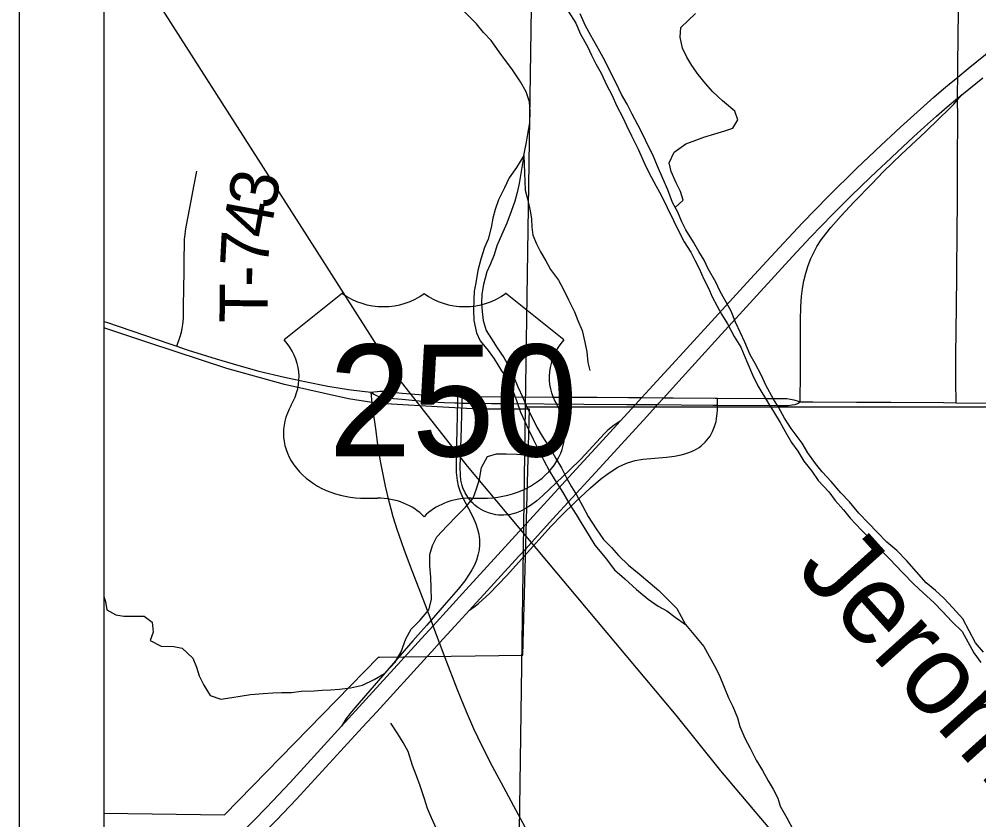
# Model space of a CAD drawing. Extents: x 0 to 34, y 0 to 22.
# Drawn here: x 9.008 to 10.139, y 9.788 to 10.732 of the extents above; entities that cross this region are included whole.
import ezdxf

# ---------------------------------------------------------------- set-up
doc = ezdxf.new("R2010")
doc.units = 0
for name, color, linetype in [('GM_X_Corporation', 7, 'Continuous'), ('GM_X_County_Road', 7, 'Continuous'), ('GM_X_Interchange_Ramps', 7, 'Continuous'), ('GM_X_Interstate_Route', 7, 'Continuous'), ('GM_X_Major_River', 7, 'Continuous'), ('GM_X_Major_River_Text', 7, 'Continuous'), ('GM_X_Minor_River', 7, 'Continuous'), ('GM_X_Rail_Line', 7, 'Continuous'), ('GM_X_Section', 7, 'Continuous'), ('GM_X_Township_Road', 7, 'Continuous'), ('GM_X_Township_Road_Text', 7, 'Continuous'), ('GM_X_US_Location', 7, 'Continuous'), ('GM_X_US_Route', 7, 'Continuous'), ('GM_X_US_Shield', 7, 'Continuous'), ('SH_Data', 7, 'Continuous')]:
    doc.layers.add(name, color=color, linetype=linetype)

msp = doc.modelspace()

# ---------------------------------------------------------------- linework, layer by layer
at = {"layer": 'GM_X_Corporation'}
msp.add_lwpolyline([(9.1079, 10.3684), (9.1079, 9.7958), (9.2501, 9.7938), (9.4314, 9.9801), (9.4329, 9.9801), (9.6019, 9.9824), (9.6097, 10.2726), (9.5496, 10.2726), (9.5073, 10.2746), (9.4404, 10.2788), (9.4239, 10.2802), (9.3964, 10.2847), (9.3206, 10.3014), (9.2529, 10.3204), (9.1608, 10.3507)], close=True, dxfattribs=at)
at = {"layer": 'GM_X_County_Road'}
msp.add_line((9.4241, 10.2795), (9.4228, 10.2923), dxfattribs=at)
for points in [[(9.5103, 9.9792), (9.5036, 9.9968), (9.4982, 10.0112), (9.496, 10.017), (9.4935, 10.0236), (9.4861, 10.0432), (9.4695, 10.0867), (9.4617, 10.1071), (9.4536, 10.1306), (9.449, 10.1455), (9.444, 10.1635), (9.4398, 10.1817), (9.4343, 10.2092), (9.4317, 10.2245), (9.4283, 10.2492), (9.4251, 10.2707), (9.4241, 10.2795)], [(9.6071, 9.7743), (9.5939, 9.7989), (9.5792, 9.8263), (9.5659, 9.8509), (9.5533, 9.8758), (9.544, 9.8955), (9.5353, 9.9155), (9.5249, 9.9415), (9.5103, 9.9792)]]:
    msp.add_lwpolyline(points, dxfattribs=at)
at = {"layer": 'GM_X_Interchange_Ramps'}
for points in [[(9.9288, 10.281), (9.9289, 10.295), (9.9291, 10.302), (9.9293, 10.3126), (9.9292, 10.3776), (9.9295, 10.3931), (9.9303, 10.4054), (9.9315, 10.4147), (9.9332, 10.4238), (9.9354, 10.4328), (9.9382, 10.4417), (9.9415, 10.4503), (9.9455, 10.4587), (9.9485, 10.4641), (9.9535, 10.472), (9.959, 10.4794), (9.9648, 10.4867), (9.9771, 10.5006), (9.9919, 10.5165), (10.0135, 10.5387), (10.0268, 10.5522), (10.0482, 10.5732), (10.0764, 10.5997), (10.0929, 10.6156), (10.1038, 10.626), (10.1099, 10.6322), (10.1145, 10.6373), (10.1195, 10.6432)], [(9.5247, 10.2879), (9.5247, 10.2869), (9.5246, 10.2799), (9.5243, 10.2693), (9.5242, 10.2631), (9.5239, 10.2506), (9.5237, 10.2288), (9.523, 10.2069), (9.5232, 10.1976), (9.5242, 10.1883), (9.5255, 10.1822), (9.5273, 10.1763), (9.531, 10.1677), (9.5413, 10.1484), (9.544, 10.1427), (9.5464, 10.137), (9.5483, 10.131), (9.5497, 10.125), (9.5505, 10.1188), (9.5506, 10.1126), (9.5501, 10.1064), (9.5489, 10.1002), (9.5471, 10.0943), (9.5447, 10.0885), (9.5418, 10.083), (9.5386, 10.0777), (9.5332, 10.07), (9.5254, 10.0602), (9.509, 10.0414), (9.4935, 10.0236), (9.4885, 10.0178), (9.4816, 10.01), (9.4722, 9.9991), (9.4037, 9.9203), (9.3979, 9.9132), (9.3935, 9.9074), (9.3879, 9.8984)], [(9.7164, 10.2582), (9.714, 10.2566), (9.7094, 10.2534), (9.7041, 10.2493), (9.7011, 10.2467), (9.6981, 10.2438), (9.67, 10.2135), (9.6568, 10.2004), (9.6253, 10.1706), (9.6183, 10.1645), (9.6109, 10.1589), (9.6057, 10.1555), (9.6002, 10.1525), (9.5945, 10.1501), (9.5916, 10.1492), (9.5856, 10.1478), (9.5794, 10.1473), (9.5732, 10.1475), (9.5701, 10.1479), (9.5641, 10.1492), (9.5611, 10.1502), (9.5554, 10.1526), (9.5526, 10.154), (9.55, 10.1556), (9.5475, 10.1574), (9.5451, 10.1594), (9.5428, 10.1615), (9.5406, 10.1637), (9.5387, 10.1661), (9.5368, 10.1686), (9.5336, 10.1739), (9.5311, 10.1796), (9.5302, 10.1825), (9.5288, 10.1885), (9.5282, 10.1947), (9.528, 10.204), (9.5294, 10.2505), (9.5299, 10.267), (9.5302, 10.2797), (9.5304, 10.2868), (9.5305, 10.2877)], [(9.7884, 10.2185), (9.7927, 10.2196), (9.7986, 10.2216), (9.8043, 10.2242), (9.8096, 10.2274), (9.8121, 10.2292), (9.8167, 10.2334), (9.8188, 10.2357), (9.8225, 10.2407), (9.8255, 10.2461), (9.8279, 10.2519), (9.8296, 10.2579), (9.8303, 10.2609), (9.8311, 10.2676), (9.8313, 10.271), (9.8314, 10.2772)], [(9.8314, 10.2772), (9.8315, 10.2843), (9.8315, 10.2855)], [(9.5388, 10.0355), (9.5457, 10.0401), (9.5495, 10.0432), (9.5544, 10.0476), (9.5624, 10.0551), (9.583, 10.0764), (9.6346, 10.1342), (9.6476, 10.1476), (9.6633, 10.1627), (9.6816, 10.1796), (9.6934, 10.1898), (9.7008, 10.1955), (9.7059, 10.1991), (9.7139, 10.2039), (9.7195, 10.2066), (9.7253, 10.209), (9.7342, 10.2117), (9.7433, 10.2134), (9.7526, 10.2144), (9.7713, 10.2157), (9.7806, 10.2169), (9.7867, 10.218), (9.7884, 10.2185)]]:
    msp.add_lwpolyline(points, dxfattribs=at)
at = {"layer": 'GM_X_Interstate_Route'}
for points in [[(10.1044, 10.6558), (10.1146, 10.6642), (10.1269, 10.6741), (10.18, 10.7171)], [(10.1195, 10.6432), (10.144, 10.6634)], [(9.7164, 10.2582), (9.7347, 10.2781), (9.742, 10.286), (9.7508, 10.2955), (9.7822, 10.33), (9.8368, 10.3895), (9.8704, 10.4262), (9.9041, 10.4628), (9.9316, 10.4922), (9.962, 10.5233), (9.9951, 10.5561), (10.0243, 10.584), (10.047, 10.6051), (10.0863, 10.6404), (10.1004, 10.6525), (10.1044, 10.6558)], [(9.7587, 10.2756), (9.7607, 10.2778), (9.7679, 10.2858), (9.7817, 10.301), (9.836, 10.3608), (9.9198, 10.4526), (9.941, 10.4754), (9.967, 10.5022), (9.989, 10.5242), (10.0114, 10.5458), (10.025, 10.5586), (10.0293, 10.5627), (10.0437, 10.5761), (10.0626, 10.5935), (10.0755, 10.6054), (10.0895, 10.618), (10.1023, 10.629), (10.1145, 10.6391), (10.1195, 10.6432)], [(9.6052, 10.1079), (9.6369, 10.1427), (9.6831, 10.1931), (9.7441, 10.2595), (9.7587, 10.2756)], [(9.1079, 9.6248), (9.1299, 9.6429), (9.1487, 9.6592), (9.1811, 9.6882), (9.2155, 9.7198), (9.247, 9.7498), (9.2691, 9.7717), (9.2996, 9.8027), (9.3274, 9.8321), (9.3798, 9.8895), (9.3879, 9.8984), (9.4865, 10.0067), (9.496, 10.017), (9.5347, 10.0594), (9.585, 10.1145), (9.6605, 10.197), (9.7003, 10.2407), (9.7164, 10.2582)], [(9.4891, 9.9807), (9.4945, 9.9866), (9.5036, 9.9968), (9.5215, 10.0166), (9.5388, 10.0355), (9.5971, 10.0991), (9.6052, 10.1079)], [(9.1079, 9.6002), (9.1393, 9.6263), (9.1674, 9.6508), (9.2021, 9.6819), (9.2318, 9.7092), (9.261, 9.7371), (9.2875, 9.7633), (9.3114, 9.7877), (9.3349, 9.8125), (9.4042, 9.8881), (9.4126, 9.8972), (9.4295, 9.9155), (9.4891, 9.9807)]]:
    msp.add_lwpolyline(points, dxfattribs=at)
at = {"layer": 'GM_X_Major_River'}
for points in [[(9.6554, 10.7417), (9.6641, 10.7276), (9.6698, 10.7147), (9.6781, 10.7002), (9.6826, 10.6899), (9.6879, 10.6797), (9.6943, 10.6686), (9.7003, 10.6549), (9.7071, 10.6423), (9.7124, 10.6305), (9.7195, 10.6164), (9.7241, 10.6069), (9.7301, 10.5947), (9.7376, 10.5791), (9.7467, 10.5586), (9.7534, 10.5456), (9.7591, 10.5353), (9.7648, 10.5247), (9.7866, 10.4805), (9.7919, 10.4698), (9.7998, 10.4576), (9.8047, 10.4481), (9.8096, 10.4382), (9.8153, 10.4256), (9.8206, 10.415), (9.8251, 10.4051), (9.8311, 10.394), (9.836, 10.3845), (9.8432, 10.3731), (9.8511, 10.3582), (9.8587, 10.3456), (9.8628, 10.3361), (9.8669, 10.3258), (9.8726, 10.3129), (9.879, 10.3)], [(9.8975, 10.2843), (9.8885, 10.3007), (9.8832, 10.3121), (9.8757, 10.3262), (9.87, 10.3365), (9.8636, 10.3513), (9.8583, 10.3624), (9.8527, 10.3749), (9.8474, 10.3879), (9.8342, 10.4119), (9.8293, 10.4221), (9.8203, 10.4381), (9.8154, 10.4481), (9.8093, 10.4583), (9.8029, 10.4694), (9.7938, 10.4839), (9.7893, 10.4934), (9.7844, 10.5048), (9.7784, 10.5162), (9.7728, 10.5311), (9.7667, 10.5444), (9.7607, 10.5589), (9.7551, 10.5726), (9.7498, 10.5821), (9.7434, 10.5962), (9.7373, 10.6076), (9.7306, 10.6202), (9.7249, 10.632), (9.7181, 10.6434), (9.7117, 10.6568), (9.7045, 10.6716), (9.6985, 10.6838), (9.6925, 10.6941), (9.6819, 10.7131), (9.6755, 10.7245), (9.6695, 10.7386)], [(9.879, 10.3), (9.8914, 10.279), (9.8975, 10.2695), (9.9054, 10.2569), (9.9111, 10.2462), (9.9186, 10.2333), (9.9262, 10.223), (9.9333, 10.2112), (9.9424, 10.1994), (9.95, 10.1883), (9.9624, 10.1749), (9.97, 10.1646), (9.9798, 10.1536), (9.9878, 10.1437), (10.001, 10.1299), (10.0124, 10.1189), (10.0207, 10.1093), (10.0343, 10.096), (10.0494, 10.0799), (10.0627, 10.0662), (10.074, 10.0559), (10.0865, 10.0444), (10.0967, 10.0337), (10.1077, 10.0219), (10.1198, 10.0101)], [(10.1206, 10.0253), (10.1089, 10.0383), (10.0983, 10.0497), (10.0885, 10.0585), (10.0775, 10.0677), (10.0661, 10.0806), (10.0544, 10.0936), (10.0427, 10.1058), (10.031, 10.1154), (10.0196, 10.1272), (10.0094, 10.1379), (9.998, 10.1497), (9.9871, 10.1631), (9.9769, 10.1737), (9.9655, 10.1871), (9.9549, 10.1985), (9.947, 10.2085), (9.9379, 10.221), (9.9311, 10.2325), (9.9183, 10.2496), (9.9104, 10.2618), (9.9032, 10.2748), (9.8975, 10.2843)], [(10.145, 9.9858), (10.1355, 9.997), (10.1206, 10.0253)], [(10.1198, 10.0101), (10.1336, 9.9852), (10.142, 9.9736)]]:
    msp.add_lwpolyline(points, dxfattribs=at)
at = {"layer": 'GM_X_Minor_River'}
for points in [[(9.6028, 10.5717), (9.6059, 10.5873), (9.6082, 10.5991), (9.6102, 10.6101), (9.6106, 10.6234), (9.6095, 10.6348), (9.6057, 10.6466), (9.599, 10.6584), (9.5888, 10.674), (9.5812, 10.6836), (9.574, 10.6938), (9.5646, 10.7072), (9.5555, 10.7167), (9.5472, 10.727), (9.5355, 10.7389), (9.5241, 10.7492), (9.5116, 10.7595), (9.4995, 10.7694)], [(9.7815, 10.5103), (9.7909, 10.5188), (9.7876, 10.5291), (9.7827, 10.5394), (9.7766, 10.5527), (9.7744, 10.563), (9.7801, 10.5755), (9.7938, 10.5853), (9.8056, 10.5898), (9.8151, 10.5932), (9.828, 10.5973), (9.8398, 10.6007), (9.8493, 10.6037), (9.8554, 10.6135), (9.8517, 10.6238), (9.8373, 10.636), (9.8259, 10.6467), (9.8172, 10.6567), (9.8086, 10.667), (9.801, 10.6776), (9.7953, 10.6875), (9.7901, 10.6982), (9.7871, 10.7111), (9.7879, 10.7225), (9.8054, 10.7392)], [(9.6028, 10.5717), (9.5944, 10.5573), (9.5856, 10.5452), (9.5803, 10.5335), (9.573, 10.5194), (9.5692, 10.5081), (9.5665, 10.4978), (9.5645, 10.4868), (9.5607, 10.4731), (9.5565, 10.4633), (9.5523, 10.4492), (9.5488, 10.4359), (9.5465, 10.4215), (9.5445, 10.4116), (9.5441, 10.4018), (9.5437, 10.3892), (9.544, 10.3771), (9.547, 10.3626), (9.5515, 10.3531), (9.561, 10.3417), (9.5678, 10.3317), (9.5768, 10.3176), (9.5833, 10.3081), (9.5897, 10.2952), (9.5942, 10.2826), (9.5991, 10.2689), (9.6043, 10.2579), (9.6085, 10.2483), (9.6138, 10.2369), (9.6213, 10.2221), (9.6266, 10.2118), (9.6334, 10.1992), (9.6398, 10.1882), (9.6488, 10.1741), (9.6575, 10.1592), (9.6647, 10.1482), (9.6707, 10.1383), (9.6798, 10.123), (9.6866, 10.112), (9.6987, 10.0975), (9.71, 10.083), (9.7221, 10.0723), (9.7358, 10.0597), (9.7494, 10.0482), (9.7615, 10.0402), (9.7714, 10.0344), (9.7812, 10.0272), (9.7937, 10.0184)], [(9.6028, 10.5717), (9.5974, 10.5387), (9.5951, 10.5281), (9.5924, 10.5178), (9.5882, 10.5057), (9.5828, 10.492), (9.5767, 10.4776), (9.5713, 10.4651), (9.5678, 10.4545), (9.5636, 10.4439), (9.5594, 10.4344), (9.5552, 10.4196), (9.5536, 10.4082), (9.5532, 10.3975), (9.5539, 10.3877), (9.555, 10.377), (9.5584, 10.3652), (9.5648, 10.3553), (9.5716, 10.3446), (9.5792, 10.3332), (9.5856, 10.3218), (9.5909, 10.3115), (9.5958, 10.2986), (9.6018, 10.286), (9.6063, 10.2746), (9.6135, 10.2609), (9.6184, 10.2513), (9.6244, 10.2407), (9.635, 10.2239), (9.6406, 10.2144), (9.6474, 10.2033), (9.6538, 10.1908), (9.6591, 10.1809), (9.6652, 10.1713), (9.6723, 10.1584), (9.6787, 10.1458), (9.6882, 10.1313), (9.6969, 10.1188), (9.7063, 10.1092), (9.7146, 10.0997), (9.7264, 10.0886), (9.7389, 10.0783), (9.7521, 10.0672), (9.7623, 10.0584), (9.7718, 10.0489), (9.7835, 10.0374), (9.7937, 10.0184)], [(9.6028, 10.5717), (9.6046, 10.5307), (9.6072, 10.5204), (9.6106, 10.5063), (9.612, 10.4965), (9.6124, 10.487), (9.6135, 10.4775), (9.618, 10.4676), (9.6225, 10.458), (9.6289, 10.4474), (9.6342, 10.4371), (9.644, 10.4245), (9.6493, 10.4142), (9.6557, 10.4013), (9.6625, 10.3872), (9.6667, 10.3769), (9.6716, 10.3651), (9.6749, 10.3514), (9.6772, 10.34), (9.6786, 10.3274), (9.6809, 10.3179)], [(9.1079, 10.0514), (9.1097, 10.0456), (9.1112, 10.0357), (9.1218, 10.03), (9.1313, 10.0284), (9.1446, 10.0284), (9.1552, 10.0283), (9.1647, 10.0211), (9.1658, 10.0093), (9.1624, 9.9994), (9.1753, 9.9929), (9.1901, 9.9925), (9.2, 9.9905), (9.2125, 9.9787), (9.217, 9.9681), (9.22, 9.9578), (9.2257, 9.9471), (9.2332, 9.9346), (9.2458, 9.9303), (9.2587, 9.9322), (9.2686, 9.9341), (9.2807, 9.9359), (9.2955, 9.937), (9.3069, 9.9377), (9.3172, 9.9381), (9.329, 9.9384), (9.3404, 9.9399), (9.3556, 9.9402), (9.3651, 9.9409), (9.3749, 9.9413), (9.3856, 9.942), (9.3985, 9.9439), (9.4129, 9.9468), (9.4263, 9.9536), (9.4388, 9.9608), (9.4514, 9.9741), (9.4583, 9.9862), (9.464, 10.0014), (9.4701, 10.0128), (9.4804, 10.023), (9.4911, 10.0359), (9.4942, 10.048), (9.4938, 10.0613), (9.4931, 10.0743), (9.492, 10.0876), (9.492, 10.1009), (9.4951, 10.1115), (9.5004, 10.1217), (9.5126, 10.135), (9.5241, 10.1467), (9.534, 10.157), (9.5431, 10.1676), (9.5473, 10.1786), (9.5508, 10.19), (9.5531, 10.2036), (9.56, 10.2165), (9.5706, 10.2199), (9.582, 10.2199), (9.5946, 10.2194), (9.604, 10.2187), (9.6162, 10.2186)], [(9.7937, 10.0184), (9.8152, 9.9924), (9.8213, 9.981), (9.8277, 9.9696), (9.8333, 9.9589), (9.839, 9.9445), (9.8443, 9.9319), (9.8492, 9.9216), (9.8548, 9.9083), (9.8578, 9.898), (9.8635, 9.8843), (9.8699, 9.8725), (9.877, 9.8584), (9.8842, 9.8462), (9.891, 9.834), (9.897, 9.8241), (9.9023, 9.8138), (9.9053, 9.804), (9.9132, 9.7906), (9.9204, 9.7761)], [(9.5058, 9.7576), (9.5001, 9.7776), (9.4941, 9.7906), (9.4892, 9.8016), (9.4854, 9.8142), (9.4809, 9.8283), (9.4764, 9.8401), (9.4715, 9.8523), (9.4667, 9.8686), (9.4606, 9.8793), (9.4542, 9.8896), (9.4463, 9.9021)]]:
    msp.add_lwpolyline(points, dxfattribs=at)
at = {"layer": 'GM_X_Rail_Line'}
msp.add_lwpolyline([(10.805, 9.1775), (10.7763, 9.2168), (10.7021, 9.273), (10.6139, 9.322), (10.4117, 9.4273), (10.1211, 9.5782), (10.0825, 9.6016), (10.0422, 9.6272), (10.0025, 9.6582), (9.9676, 9.6941), (9.9058, 9.7623), (9.8351, 9.846), (9.7824, 9.9117), (9.5366, 10.2052), (9.4517, 10.3134), (9.3656, 10.4485), (9.1289, 10.8193), (9.1079, 10.8523)], dxfattribs=at)
at = {"layer": 'GM_X_Section'}
for points in [[(9.6203, 11.2953), (10.6237, 11.2801), (10.6178, 10.275), (9.605, 10.2746)], [(10.6178, 10.275), (10.6118, 9.2695), (9.5908, 9.2763), (9.605, 10.2746)]]:
    msp.add_lwpolyline(points, close=True, dxfattribs=at)
at = {"layer": 'GM_X_Township_Road'}
for points in [[(10.1126, 10.28), (10.1125, 10.3049), (10.1122, 10.3163), (10.1123, 10.338), (10.1128, 10.3628), (10.1137, 10.428), (10.1141, 10.487), (10.1143, 10.5118), (10.1145, 10.5646), (10.1146, 10.6173), (10.1145, 10.6373), (10.1145, 10.6391), (10.1145, 10.6453), (10.1146, 10.6642), (10.1147, 10.6732), (10.1152, 10.7167), (10.1157, 10.757)], [(9.1938, 10.3466), (9.1976, 10.3581), (9.1992, 10.3632), (9.2001, 10.3675), (9.2008, 10.3722), (9.2015, 10.3798), (9.2016, 10.3861), (9.2017, 10.3926), (9.2021, 10.4159), (9.2024, 10.4338), (9.2026, 10.4497), (9.2029, 10.4676), (9.203, 10.4728), (9.2035, 10.4783), (9.204, 10.4824), (9.2048, 10.4873), (9.2071, 10.4995), (9.2106, 10.518), (9.2139, 10.5349), (9.2174, 10.5533)]]:
    msp.add_lwpolyline(points, dxfattribs=at)
at = {"layer": 'GM_X_US_Route'}
for points in [[(9.1079, 10.3759), (9.1108, 10.3749), (9.1856, 10.3494), (9.1938, 10.3466), (9.2048, 10.3428), (9.2071, 10.3421), (9.2402, 10.3317), (9.2668, 10.3238), (9.2906, 10.3174), (9.3206, 10.3101), (9.3448, 10.3049), (9.372, 10.2997), (9.3964, 10.2957), (9.4122, 10.2935), (9.4228, 10.2923)], [(9.4228, 10.2923), (9.4259, 10.293), (9.4299, 10.2934), (9.4331, 10.2935), (9.4368, 10.2936), (9.4404, 10.2934), (9.4593, 10.2914), (9.4841, 10.2894), (9.5007, 10.2887), (9.5124, 10.2883), (9.5247, 10.2879), (9.5283, 10.2878), (9.5305, 10.2877), (9.55, 10.2873), (9.6367, 10.2864), (9.6893, 10.2864), (9.7264, 10.2862), (9.742, 10.286), (9.7679, 10.2858), (9.7791, 10.2857), (9.8286, 10.2855), (9.8315, 10.2855), (9.8874, 10.2849), (9.9132, 10.2849), (9.9174, 10.2844), (9.9213, 10.2835), (9.9253, 10.2823), (9.9288, 10.281)], [(9.4228, 10.2923), (9.426, 10.2901), (9.4291, 10.2884), (9.4329, 10.2869), (9.4361, 10.2862), (9.4389, 10.2859), (9.4596, 10.2841), (9.4875, 10.2816), (9.5092, 10.2804), (9.5215, 10.28), (9.5246, 10.2799), (9.5302, 10.2797), (9.537, 10.2795), (9.5649, 10.2791), (9.5742, 10.279), (9.5804, 10.279), (9.6736, 10.2784), (9.7246, 10.2781)], [(9.7246, 10.2781), (9.7326, 10.2781), (9.7347, 10.2781), (9.7607, 10.2778), (9.7885, 10.2776), (9.8258, 10.2772), (9.8314, 10.2772), (9.9034, 10.2768), (9.9142, 10.2767), (9.9194, 10.2774), (9.9229, 10.2781), (9.9257, 10.2792), (9.9288, 10.281)], [(9.9288, 10.281), (9.9438, 10.281), (9.9954, 10.2807), (10.0357, 10.2805), (10.0977, 10.2803), (10.1126, 10.28)], [(10.1126, 10.28), (10.2292, 10.2788), (10.254, 10.2784), (10.3286, 10.2781), (10.3877, 10.2777), (10.425, 10.2772), (10.4841, 10.2771), (10.5557, 10.2769), (10.593, 10.2764), (10.6202, 10.2765), (10.6458, 10.2765), (10.6707, 10.2764), (10.7329, 10.2761), (10.7889, 10.2762), (10.8604, 10.2763), (10.8704, 10.2762)]]:
    msp.add_lwpolyline(points, dxfattribs=at)
at = {"layer": 'GM_X_US_Shield'}
for p, q in [((9.3892, 10.4091), (9.3205, 10.3542)), ((9.6501, 10.3542), (9.5815, 10.4091)), ((9.4167, 10.1674), (9.4304, 10.1674)), ((9.5403, 10.1674), (9.554, 10.1674))]:
    msp.add_line(p, q, dxfattribs=at)
for centre, major_axis, start_param, end_param in [((9.4373, 10.4483), (-0.0687, 0), 0.795399, 2.346194), ((9.5334, 10.4483), (-0.0687, 0), 0.795399, 2.346194), ((9.2418, 10.3101), (0.0961, 0), 5.838949, 6.894067), ((9.7289, 10.3101), (-0.0961, 0), 5.672304, 6.727422), ((9.4156, 10.2443), (0.0961, 0), 2.702327, 4.723529), ((9.5551, 10.2443), (-0.0961, 0), 1.559657, 3.580859), ((9.4304, 10.1125), (-0.0687, 0), 3.785094, 4.712389), ((9.5403, 10.1125), (-0.0687, 0), 4.712389, 5.639684)]:
    msp.add_ellipse(centre, major_axis=major_axis, ratio=0.8, start_param=start_param, end_param=end_param, dxfattribs=at)
at = {"layer": 'SH_Data'}
for p, q in [((9.0079, 16.0775), (9.0079, 9.0775)), ((9.1079, 15.9775), (9.1079, 9.1775))]:
    msp.add_line(p, q, dxfattribs=at)

# ---------------------------------------------------------------- texts
at = {"layer": 'GM_X_Major_River_Text'}
msp.add_text('Jerome Fork', height=0.094729, rotation=311.9915, dxfattribs=at).set_placement((9.9224, 10.0819))
at = {"layer": 'GM_X_Township_Road_Text'}
for s, rotation, p in [('3', 79.5657, (9.3092, 10.5066)), ('4', 79.6342, (9.3029, 10.4722)), ('7', 87.0742, (9.3014, 10.4392)), ('-', 89.477, (9.3012, 10.4165)), ('T', 89.4857, (9.3008, 10.374))]:
    msp.add_text(s, height=0.0568, rotation=rotation, dxfattribs=at).set_placement(p)
at = {"layer": 'GM_X_US_Location'}
for s, p in [('0', (9.4854, 10.2827)), ('/', (9.4855, 10.2827))]:
    msp.add_text(s, height=0.000189, dxfattribs=at).set_placement(p)
msp.add_text('250', height=0.000189, rotation=0, dxfattribs=at).set_placement((9.4272, 10.2435))
at = {"layer": 'GM_X_US_Shield'}
msp.add_text('250', height=0.13184, dxfattribs=at).set_placement((9.3726, 10.2168))

doc.saveas('drawing.dxf')
